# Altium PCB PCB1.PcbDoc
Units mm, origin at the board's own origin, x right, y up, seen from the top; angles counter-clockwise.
Board outline 49.91 x 77.34 mm, 4 copper layers (Top Layer, Layer 1, Layer 2, Bottom Layer), stack 0.787 mm thick; 22 components, 20 nets, 113 pads, 11 vias.
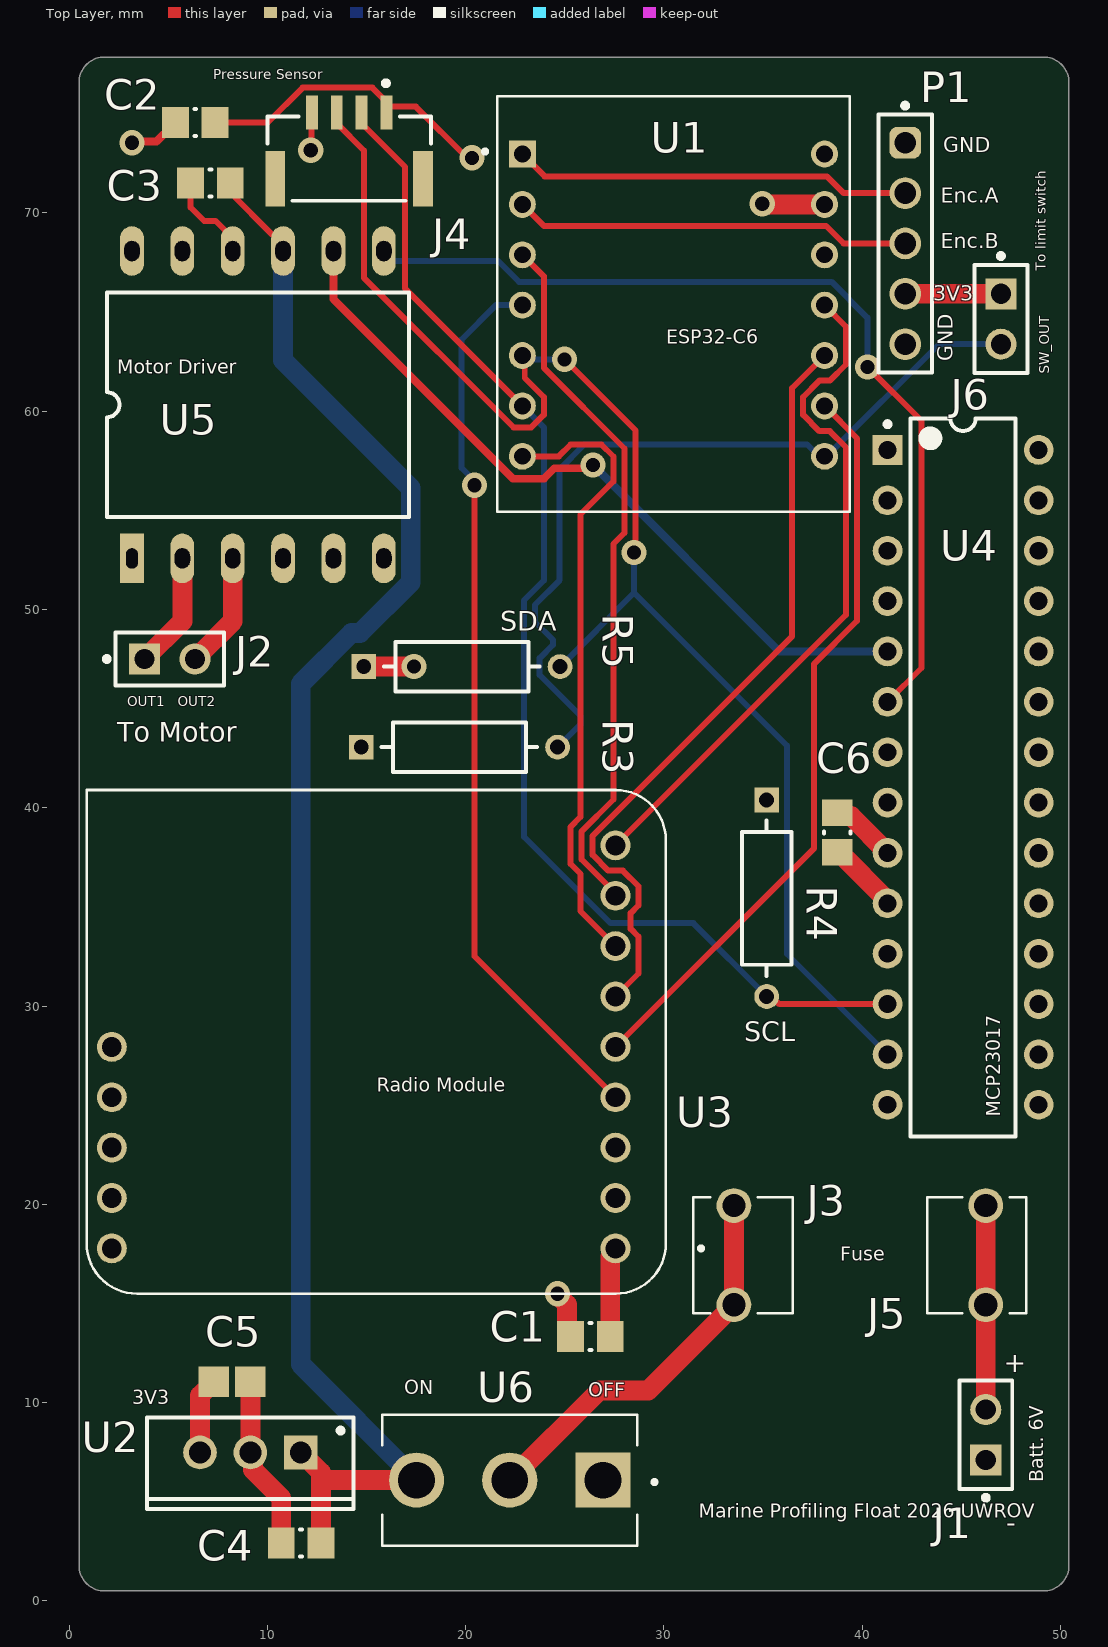
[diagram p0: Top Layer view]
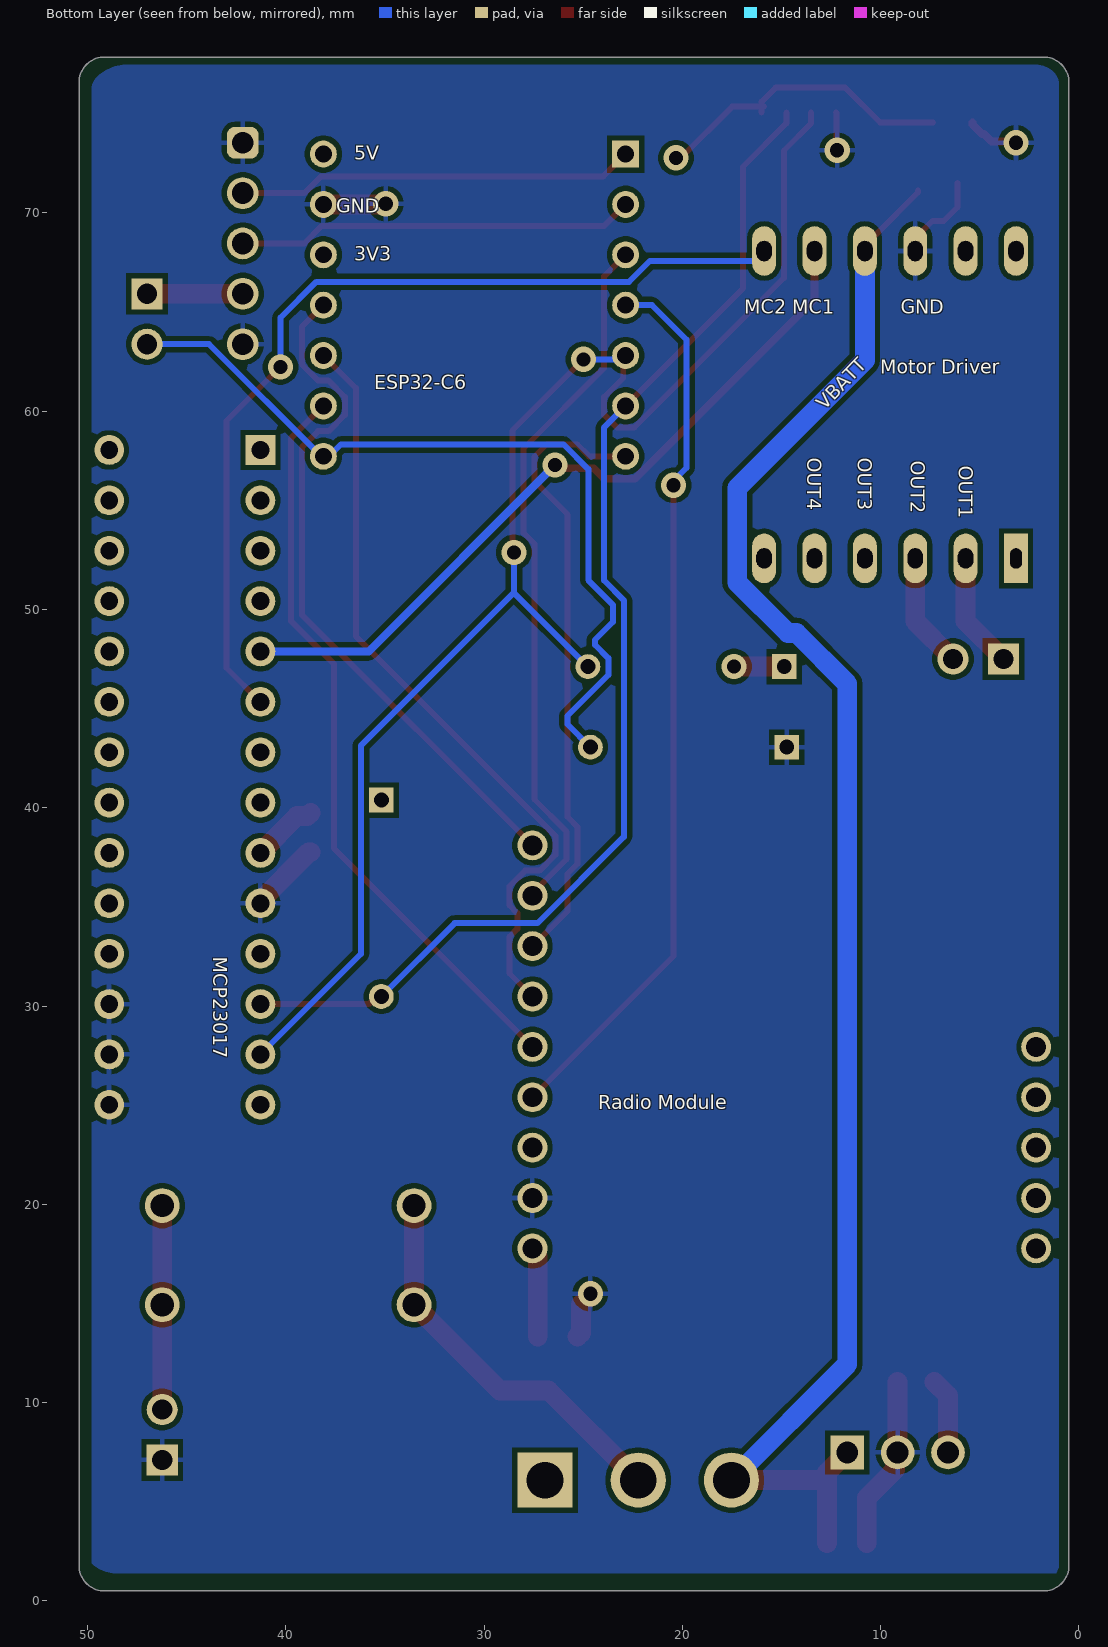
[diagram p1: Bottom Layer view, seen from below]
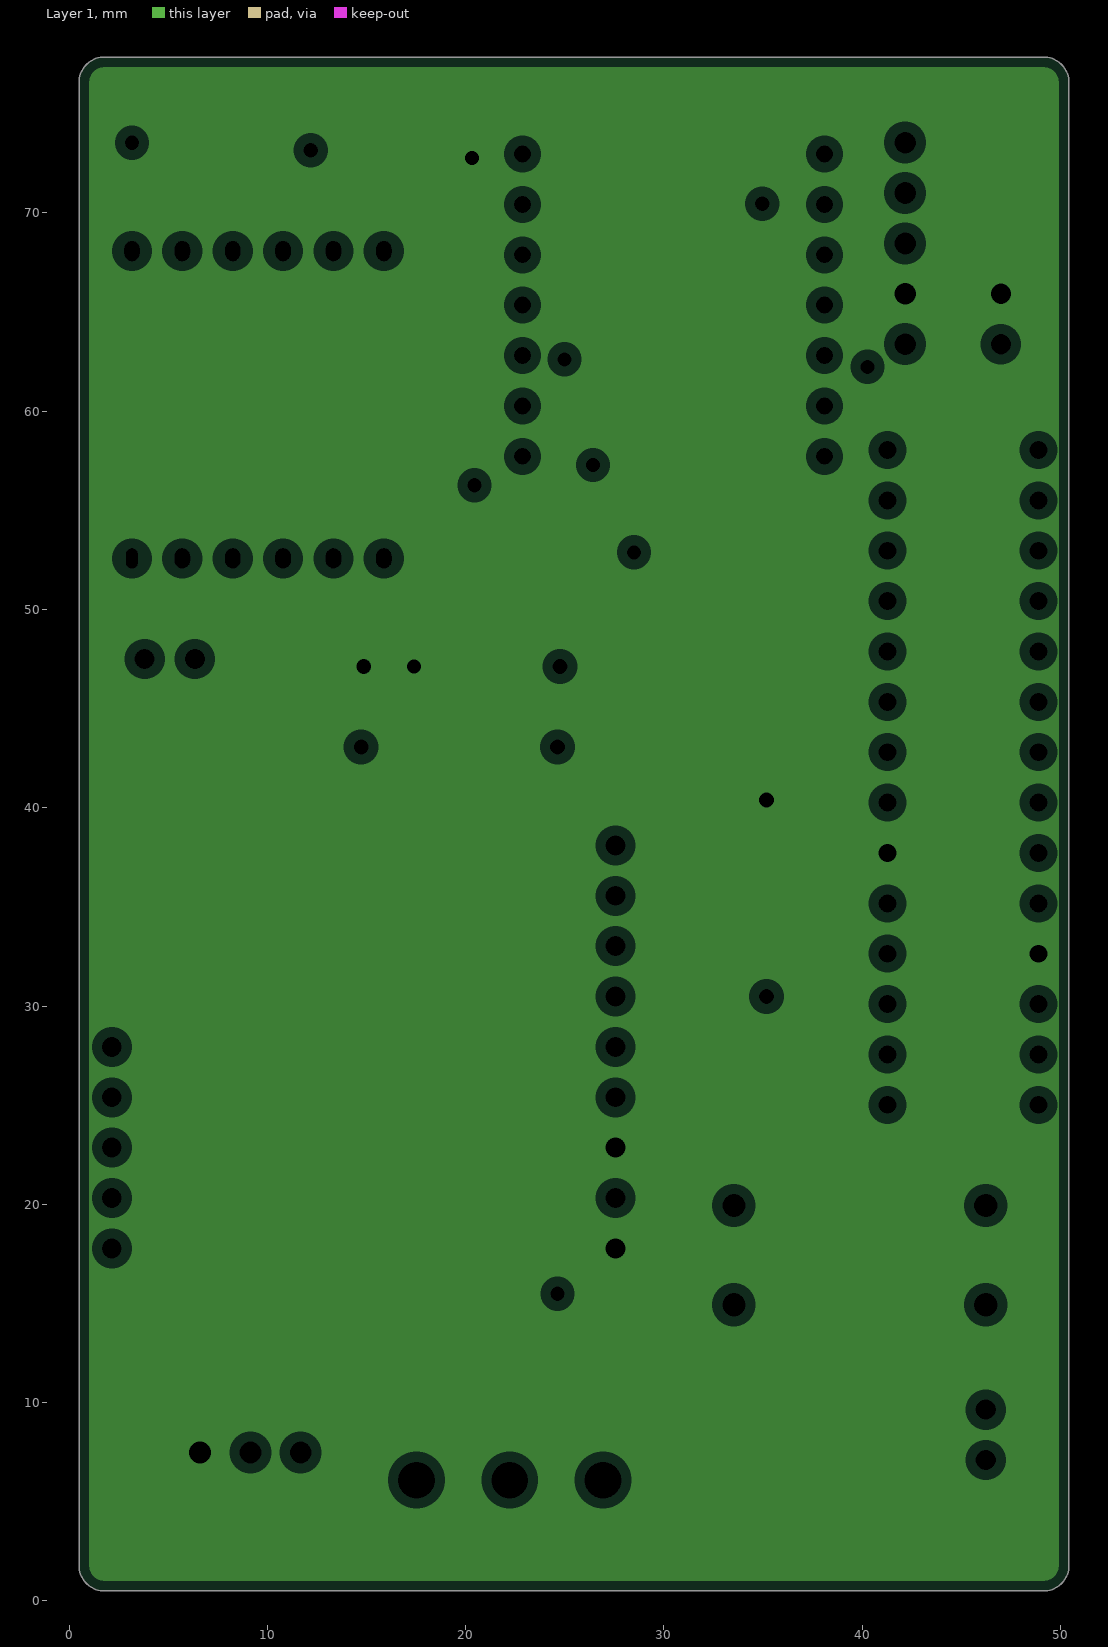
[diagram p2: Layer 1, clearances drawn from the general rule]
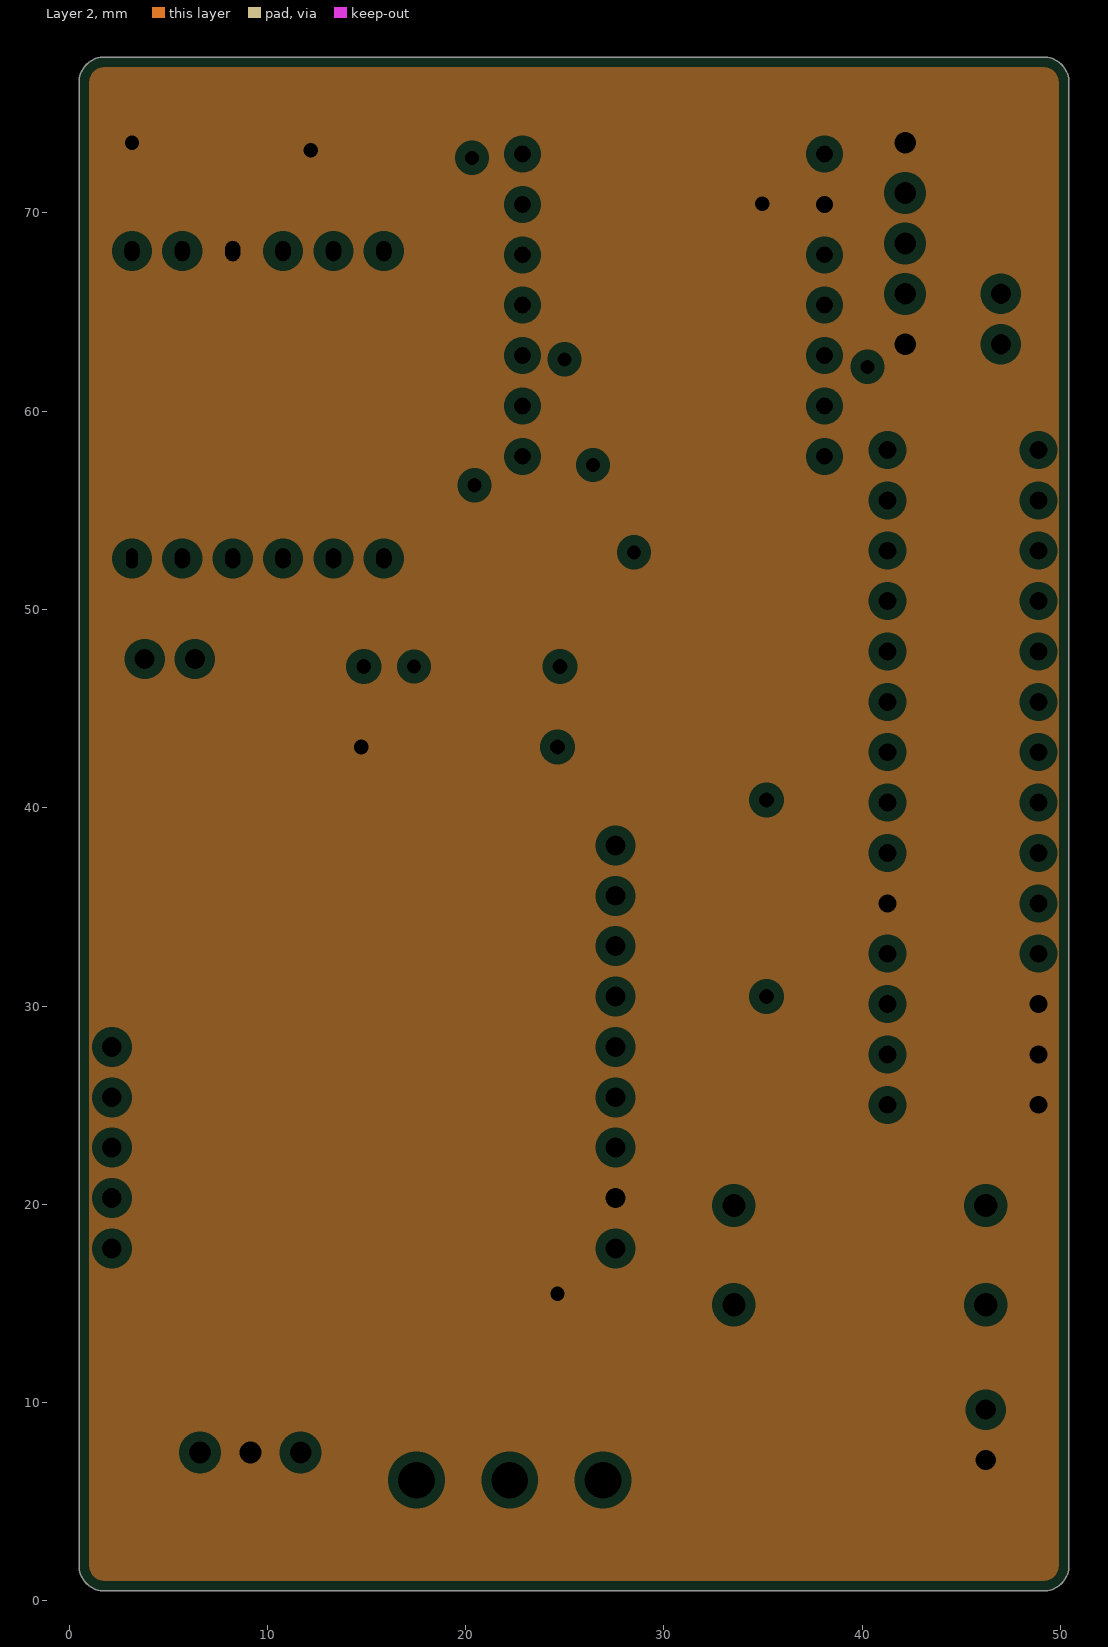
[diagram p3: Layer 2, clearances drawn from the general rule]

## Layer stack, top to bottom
Top Solder: solder mask 0.0102, Solder Resist, Dk 3.5
Top Layer: signal copper 0.0356
Dielectric 2: prepreg 0.1803, PP-021, Dk 4.4
Layer 1: plane copper 0.0175, net 3V3
Dielectric 1: dielectric 0.32, FR-4, Dk 4.8
Layer 2: plane copper 0.0175, net GND
Dielectric 3: prepreg 0.1803, PP-021, Dk 4.4
Bottom Layer: signal copper 0.0356
Bottom Solder: solder mask 0.0102, Solder Resist, Dk 3.5

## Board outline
0.508,1.778 0.508,76.581 cw(c1.778,76.581) 1.778,77.851 49.149,77.851 cw(c49.149,76.581) 50.419,76.581 50.419,1.778 cw(c49.149,1.778) 49.149,0.508 1.778,0.508 cw(c1.778,1.778)

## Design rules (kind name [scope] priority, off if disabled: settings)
Clearance [All] p1: gap=0.254 ignorepadtopadclearanceinfootprint=FALSE
PlaneClearance [All] p1: clearance=0.508
PlaneConnect [All] p1: planeconnectstyle=Relief reliefexpansion=0.508 reliefentries=4 reliefconductorwidth=0.254 reliefairgap=0.254
PolygonConnect [All] p1: connectstyle=Relief reliefconductorwidth=0.254 reliefentries=4 polygonreliefangle="90 Angle" airgapwidth=0.254
RoutingVias [All] p1: holewidth=0.711 width=1.27 viastyle="Through Hole" minholewidth=0.711 minwidth=1.27 maxholewidth=0.711 maxwidth=1.27
SolderMaskExpansion [All] p1: expansion=0.102 istentingtop=FALSE
SupplyNets "Schematic Supply Nets_1" [InNet('GND')] p1: voltage=0.000
SupplyNets "Schematic Supply Nets" [InNet('3V3')] p2: voltage=0.000
Width [All] p1: maxlimit=1 minlimit=0.254 preferedwidth=0.3
28 further rules are at their usual default settings.

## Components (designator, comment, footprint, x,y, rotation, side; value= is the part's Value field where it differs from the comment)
C1 "CAP 100nF 10V 0805(2012)" CAPC0805(2012)100_M 26.289,13.335 r0 top value=100nF
C2 "CAP 100nF 10V 0805(2012)" CAPC0805(2012)100_M 6.366,74.549 r0 top value=100nF
C3 "CAP 100nF 10V 0805(2012)" CAPC0805(2012)100_M 7.128,71.501 r180 top value=100nF
C4 "CAP 100nF 10V 0805(2012)" CAPC0805(2012)100_M 11.7,2.921 r0 top value=100nF
C5 "08053C225MAT2A" CAPC2013X152X50ML20T25 8.219,11.049 r180 top
C6 "CAP 100nF 10V 0805(2012)" CAPC0805(2012)100_M 38.735,38.751 r90 top value=100nF
J1 "TSW-102-07-F-S" FP-TSW-102-07-F-S-MFG 46.228,8.382 r90 top
J2 "TSW-102-07-F-S" FP-TSW-102-07-F-S-MFG 5.08,47.498 r0 top
J3 "Fuse Holder" FUSE_01110501Z 33.988,17.439 r0 top
J4 "BM04B-GHS-TBT(LF)(SN)" FP-BM04B-GHS-TBT_LF_SN-MFG 14.127,72.732 r0 top
J5 "Fuse Holder" FUSE_01110501Z 45.768,17.439 r180 top
J6 "TSW-102-07-F-S" FP-TSW-102-07-F-S-MFG 46.99,64.643 r270 top
P1 "61300511121" 61300511121 42.164,68.453 r270 top
R3 "RCMM024701GKS14" FP-RCMM02-MFG 19.685,43.053 r0 top
R4 "RCMM024701GKS14" FP-RCMM02-MFG 35.179,35.433 r270 top
R5 "RCMM024701GKS14" FP-RCMM02-MFG 19.812,47.117 r0 top
U1 "XIAO_ESP32_C6" MODULE_XIAO_ESP32C6 30.48,65.405 r0 top
U2 "LF33CV" TO220 9.144,7.493 r180 top
U3 "Component_1" RFM9X_LoRa 15.494,28.194 r180 top
U4 "MCP23017-E/SP" SPDIP300-SP28 45.085,41.529 r0 top
U5 "DRV8833" "DRV8833 Motor Driver" 3.175,52.572 r90 top
U6 "EG5137-ND" SW_500SSP1S2M2QEA 22.224,6.096 r180 top

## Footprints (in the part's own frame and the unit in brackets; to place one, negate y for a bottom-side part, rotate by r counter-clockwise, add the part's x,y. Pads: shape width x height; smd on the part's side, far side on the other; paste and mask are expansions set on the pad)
61300511121 [mm] "Pin Header, pitch 2.54 mm, THT, Vertical, single row, 5p"
  rrect50% 1.6x1.6 hole 1.1: 1(-5.08,0)
  round 1.6 hole 1.1: 2(-2.54,0) 3(0,0) 4(2.54,0) 5(5.08,0)
  silkscreen extent -7.07,-1.35 6.5,1.35, body extent -6.35,-1.27 6.35,1.27, height 8.57
CAPC0805(2012)100_M [mm] "Chip Capacitor, Body 2.0x1.2mm, Height 1.0mm, IPC Low Density"
  rect 1.35x1.55 smd: 1(-1,0) 2(1,0)
  silkscreen extent -0.05,-0.67 0.05,0.67, body extent -1.1,-0.72 1.1,0.72, height 1
CAPC2013X152X50ML20T25 [mm] "Chip Capacitor, 2-Leads, Body 2.01x1.25mm, IPC Low Density"
  rect 1.55x1.55 smd: 1(-0.925,0) 2(0.925,0)
  body extent -1.1,-0.72 1.11,0.72, height 1.52
"DRV8833 Motor Driver" [mm]
  rect 2.5x1.2 hole 0.6 slot 1.016 at 0 deg: 1(0,0)
  oval 2.5x1.2 hole 0.778 slot 1.016 at 0 deg: 2(0,-2.54) 3(0,-5.08) 4(0,-7.62) 5(0,-10.16) 6(0,-12.7) 7(15.5,-12.7) 8(15.5,-10.16) 9(15.5,-7.62) 10(15.5,-5.08) 11(15.5,-2.54) 12(15.5,0)
  silkscreen extent 2.08,-13.97 13.41,1.27
FP-BM04B-GHS-TBT_LF_SN-MFG [mm]
  rect 0.6x1.7 smd paste+0 mask+0: 1(1.875,2.325) 2(0.625,2.325) 3(-0.625,2.325) 4(-1.875,2.325)
  rect 1x2.8 smd paste+0 mask+0: 5(-3.725,-1.025) 6(3.725,-1.025)
  silkscreen extent -4.13,-2.12 4.13,3.92, body extent -4.33,-2.52 4.33,3.27, height 0.25
FP-RCMM02-MFG [mm]
  rect 1.25x1.25 hole 0.75 paste-2539.97 mask+0: 1(-4.95,0)
  round 1.25 hole 0.75 paste-2539.97 mask+0: 2(4.95,0)
  silkscreen extent -3.93,-1.25 3.93,1.25, body extent -5.68,-1.35 5.68,1.35, height 0.25
FP-TSW-102-07-F-S-MFG [mm]
  rect 1.57x1.57 hole 1.02 paste-2539.97 mask+0: 1(-1.27,0)
  round 1.57 hole 1.02 paste-2539.97 mask+0: 2(1.27,0)
  silkscreen extent -3.3,-1.34 2.73,1.34, body extent -2.83,-1.44 2.83,1.44, height 0.25
FUSE_01110501Z [mm]
  round 1.755 hole 1.17 mask+0.102: 1(-0.46,2.5) 2(-0.46,-2.5)
  silkscreen extent -2.5,-2.92 2.5,2.92
MODULE_XIAO_ESP32C6 [mm]
  rect 1.358x1.358 / inner round 1.358 / far side rect 1.358x1.358 hole 0.85 mask+0.102: 1(-7.62,7.556)
  round 1.358 hole 0.85 mask+0.102: 2(-7.62,5.016) 3(-7.62,2.476) 4(-7.62,-0.064) 5(-7.62,-2.603) 6(-7.62,-5.143) 7(-7.62,-7.683) 8(7.62,-7.683) 9(7.62,-5.143) 10(7.62,-2.603) 11(7.62,-0.064) 12(7.62,2.476) 13(7.62,5.016) 14(7.62,7.556)
  silkscreen extent -9.6,-10.48 8.89,10.48, body extent -8.89,-10.48 8.89,11.99, height 4.21
RFM9X_LoRa [mm] "RFM9X_LoRa"
  round 1.508 hole 1: U3_1(-12.065,10.414) U3_2(-12.065,7.874) U3_3(-12.065,5.334) U3_4(-12.065,2.794) U3_5(-12.065,0.254) U3_6(-12.065,-2.286) U3_7(-12.065,-4.826) U3_8(-12.065,-7.366) U3_9(-12.065,-9.906) U3_10(13.335,10.414) U3_11(13.335,7.874) U3_12(13.335,5.334) U3_13(13.335,2.794) U3_14(13.335,0.254)
  silkscreen extent -16.47,-12.7 14.61,12.7, body extent -14.61,-12.7 14.61,12.7, height 3.37
SPDIP300-SP28 [mm] "DIP, 28-Pin, Row Spacing 7.62 mm, Pitch 2.54 mm"
  rect 1.5x1.5 hole 0.9: 1(-3.81,16.51)
  round 1.5 hole 0.9: 2(-3.81,13.97) 3(-3.81,11.43) 4(-3.81,8.89) 5(-3.81,6.35) 6(-3.81,3.81) 7(-3.81,1.27) 8(-3.81,-1.27) 9(-3.81,-3.81) 10(-3.81,-6.35) 11(-3.81,-8.89) 12(-3.81,-11.43) 13(-3.81,-13.97) 14(-3.81,-16.51) 15(3.81,-16.51) 16(3.81,-13.97) 17(3.81,-11.43) 18(3.81,-8.89) 19(3.81,-6.35) 20(3.81,-3.81) 21(3.81,-1.27) 22(3.81,1.27) 23(3.81,3.81) 24(3.81,6.35) 25(3.81,8.89) 26(3.81,11.43) 27(3.81,13.97) 28(3.81,16.51)
  silkscreen extent -3.93,-18.1 2.65,18.1, body extent -3.55,-18.1 3.55,18.1, height 5.33
SW_500SSP1S2M2QEA [mm]
  rect 2.775x2.775 / inner round 2.775 / far side rect 2.775x2.775 hole 1.85 mask+0.102: 1(-4.7,0)
  round 2.775 hole 1.85 mask+0.102: 2(0,0) 3(4.7,0)
  silkscreen extent -7.4,-3.3 6.43,3.3
TO220 [mm] "TO, Thru-Hole, Vertical, Heatsink Mounted; 3 In-Line Leads; Pitch 2.54 mm"
  rect 1.7x1.7 hole 1.1: 1(-2.54,0)
  round 1.7 hole 1.1: 2(0,0) 3(2.54,0)
  silkscreen extent -5.2,-1.75 5.2,2.85, body extent -5.25,-1.8 5.25,2.9, height 19.7

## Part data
C1 C2 C3 C4 C6: library part CMP-1036-04393-1, "CAP 100nF 10V ±5% 0805 (2012 Metric) Thickness 1mm SMD", Case-EIA=0805, Case-Metric=2012, Rated Voltage="10 V", Tolerance=Â±5%
C5: library part CMP-2007-04515-1, Manufacturer="AVX Interconnect / Elco"
J1 J2 J6: library part CMP-02766-001458-1, "CONN HEADER VERT 2POS 2.54MM", Color=Black, Flammability Rating="UL94 V-0", Max Current Rating=7.6A, Max Operating Temperature=125°C, Max Voltage Rating (AC)=550V, Min Operating Temperature=-55°C, Package Quantity=1
J3 J5: library part Fuse_Holder
J4: library part CMP-17439-000062-2, "CONN HEADER SMD 4POS 1.25MM", Case/Package=SMD/SMT, Current Rating=1A, Housing Color=Natural, Max Operating Temperature=85°C, Min Operating Temperature=-25°C, Voltage Rating=50V
P1: library part CMP-1502-01068-4, "THT Vertical Pin Header WR-PHD, Pitch 2.54 mm, Single Row, 5 pins", Color=Black, Contact Resistance=20mΩ, Current Rating=3A, Max Operating Temperature=105°C, Min Operating Temperature=-40°C, Operating Supply Voltage=250V
R3 R4 R5: library part CMP-02408-000034-1, "RES 4.7K OHM 2% 1/2W AXIAL", Case/Package=Molded, Resistance=4.7kR, Resistor Type="Metal Film", Temperature Coefficient=100ppm/°C, Tolerance=2%
U1: "seeed studio FCC ID:Z4T-XIAOESP32C6"
U2: library part CMP-0244-00432-1, "500mA, Very Low Drop (0.45V) Voltage Regulator, 3.3V, 3-Pin TO-220"
U4: library part CMP-0186-00081-2, "16-Bit I/O Expander with Serial Interface, 28-Pin SPDIP, Extended Temperature"
U5: "Motor Driver 6.5V-45VDC In"
U6: library part 500SSP1S2M2QEA, "Switch Slide ON None ON SPDT Extended Top Slide 5A 250VAC 28VDC PC Pins Thru-Hole", Contact Current Rating=2A, Contact Resistance=10mΩ, Contact Voltage Rating (AC)=250V, Current Rating=5A, Insulation Resistance=1GΩ, Manufacturer=E-Switch, Max Operating Temperature=85°C, Max Voltage Rating (DC)=28V, Min Operating Temperature=-30°C, Voltage Rating (AC)=120V

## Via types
v1: diameter 1.27, hole 0.711, Top Layer to Bottom Layer, 11 vias

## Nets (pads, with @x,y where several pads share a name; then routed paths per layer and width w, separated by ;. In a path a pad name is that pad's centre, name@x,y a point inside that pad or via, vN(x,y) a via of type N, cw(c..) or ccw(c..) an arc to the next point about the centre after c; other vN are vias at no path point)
3V3: C1.2 C2.2 C5.2 C6.2 J4.1 J6.1 P1.4 R4.1 R5.1 U2.3 U3.U3_1 U3.U3_3 U4.9 U4.18 | length 34.9
  Top Layer w0.3: C2.2 10.023,74.549 11.785,76.311 15.298,76.311 16.002,75.607 J4.1 ; J4.1@15.875,75.35 17.487,75.35 20.066,72.771 v1(20.32,72.771)
  Top Layer w1: U2.3 6.604,10.359 C5.2 ; R5.1 v1(17.399,47.117) ; C1.2 27.289,17.373 27.559,17.643 U3.U3_1 ; C6.2 38.91,39.576 39.426,39.576 41.275,37.727 U4.9 ; P1.4 J6.1
ENCODER_A: P1.2 U1.1 | length 20.1
  Top Layer w0.3: U1.1 23.984,71.837 38.216,71.837 39.06,70.993 P1.2
ENCODER_B: P1.3 U1.2 | length 20.1
  Top Layer w0.3: U1.2 23.943,69.338 38.175,69.338 39.06,68.453 P1.3
GND: C1.1 C2.1 C3.2 C4.1 C5.1 C6.1 J1.1 J4.4 P1.1 P1.5 R3.1 U1.13 U2.2 U3.U3_2 U4.10 U4.15 U4.16 U4.17 U5.10 | length 27.3
  Top Layer w0.3: C3.2 6.128,70.276 6.819,69.585 7.392,69.585 8.255,68.722 U5.10 ; v1(12.192,73.152) 12.222,73.182 12.222,75.027 J4.4
  Top Layer w0.4: v1(3.175,73.533) 3.235,73.593 4.41,73.593 4.791,73.974 4.891,73.974 5.366,74.449 C2.1
  Top Layer w1: C5.1 U2.2 9.278,7.359 9.278,6.618 10.7,5.196 C4.1 ; v1(24.638,15.494) 24.638,15.421 25.114,14.945 25.114,13.51 C1.1 ; v1@34.925,70.485 34.989,70.421 U1.13 ; C6.1 38.835,37.751 41.275,35.311 U4.10
  other v1: 34.957,70.453
MC1: U4.5 U5.8 | length 38.3
  Top Layer w0.4: U5.8 13.335,65.644 22.391,56.588 23.941,56.588 24.47,57.118 26.257,57.118 v1(26.416,57.277)
  Bottom Layer w0.4: v1(26.416,57.277) 35.814,47.879 U4.5
MC2: U4.6 U5.7 | length 47
  Top Layer w0.3: v1(40.259,62.23) 42.983,59.506 42.983,47.047 U4.6
  Bottom Layer w0.3: U5.7 15.875,67.988 16.291,67.572 21.638,67.572 22.69,66.52 38.453,66.52 40.259,64.714 v1(40.259,62.23)
NetJ2_1: J2.1 U5.2 | length 5.9
  Top Layer w1: J2.1 5.715,49.403 U5.2
NetJ2_2: J2.2 U5.3 | length 5.9
  Top Layer w1: J2.2 8.255,49.403 U5.3
RADIO_CS: U1.3 U3.U3_8 | length 36.1
  Top Layer w0.3: U1.3 23.943,66.798 23.943,62.181 28.009,58.115 28.009,53.862 27.454,53.307 27.454,40.416 25.847,38.809 25.847,37.391 27.559,35.679 U3.U3_8
RADIO_G0_INT: U1.4 U3.U3_4 | length 45.2
  Top Layer w0.3: v1(20.447,56.261) 20.447,32.512 U3.U3_4
  Bottom Layer w0.3: v1(20.447,56.261) 20.447,56.479 19.789,57.137 19.789,63.604 21.526,65.341 U1.4
RADIO_MISO: U1.10 U3.U3_6 | length 39.4
  Top Layer w0.3: U3.U3_6 28.717,31.638 28.717,33.5 28.321,33.896 28.321,34.684 28.717,35.08 28.717,36.04 27.927,36.83 27.191,36.83 26.401,37.62 26.401,38.58 36.463,48.642 36.463,61.165 U1.10
RADIO_MOSI: U1.11 U3.U3_9 | length 34.9
  Top Layer w0.3: U3.U3_9 39.183,49.724 39.183,58.17 38.362,58.991 37.838,58.991 37.017,59.813 37.017,60.71 37.838,61.531 38.362,61.531 39.183,62.353 39.183,64.258 U1.11
RADIO_RST: U1.7 U3.U3_7 | length 31.6
  Top Layer w0.3: U1.7 24.699,57.721 25.294,58.316 26.846,58.316 27.455,57.707 27.455,56.454 25.791,54.791 25.791,39.537 25.293,39.039 25.293,37.161 25.791,36.663 25.791,34.788 U3.U3_7
RADIO_SCK: U1.9 U3.U3_5 | length 38
  Top Layer w0.3: U3.U3_5 37.556,37.937 37.556,47.241 39.737,49.422 39.737,58.625 U1.9
SCL: J4.2 R4.2 U1.6 U4.12 | length 62.6
  Top Layer w0.3: J4.2 14.752,74.507 16.948,72.311 16.948,66.174 U1.6 ; R4.2 35.436,30.483 35.82,30.099 U4.12
  Bottom Layer w0.3: U1.6 23.943,59.178 23.943,51.455 22.946,50.459 22.946,38.535 27.303,34.178 31.484,34.178 R4.2
SDA: J4.3 R5.2 U1.5 U4.13 | length 74.4
  Top Layer w0.3: J4.3 13.502,74.507 14.871,73.138 14.871,66.719 22.411,59.178 23.309,59.178 23.943,59.813 23.943,60.71 22.981,61.673 22.981,62.681 U1.5 ; v1(24.982,62.611) 28.575,59.018 28.575,52.959 v1(28.493,52.877)
  Bottom Layer w0.3: U1.5@22.479,62.611 v1(24.982,62.611) ; R5.2 28.493,50.848 ; v1(28.493,52.877) 28.493,50.848 ; U4.13 36.208,32.626 36.208,43.132 28.493,50.848
SWITCH_OUT: J6.2 R3.2 U1.8 | length 41.9
  Bottom Layer w0.3: R3.2 25.791,44.209 25.791,44.633 23.733,46.691 23.733,47.543 24.405,48.215 24.405,48.464 23.5,49.369 23.5,50.229 24.743,51.472 24.743,57.073 25.986,58.316 37.219,58.316 37.814,57.721 U1.8 38.215,57.721 43.867,63.373 J6.2
TERM_1: J3.1 J3.2 U6.2 | length 20
  Top Layer w1: U6.2 26.743,10.615 29.204,10.615 J3.2 J3.1
TERM_2: J1.2 J5.1 J5.2 | length 10.3
  Top Layer w1: J1.2 J5.1 J5.2
VBATT: C3.1 C4.2 U2.1 U5.9 U6.3 | length 83.3
  Top Layer w0.3: C3.1@8.128,71.12 8.128,71.02 10.254,68.894 10.379,68.894 10.795,68.478 U5.9
  Top Layer w1: U2.1 12.7,6.477 12.7,6.096 C4.2 ; 13.081,6.096 U6.3
  Bottom Layer w1: U5.9 10.795,62.562 17.229,56.128 17.229,51.361 14.676,48.808 14.237,48.808 11.684,46.255 11.684,11.936 U6.3
pads on no net: J4.5 J4.6 U1.12 U1.14 U3.U3_10 U3.U3_11 U3.U3_12 U3.U3_13 U3.U3_14 U4.1 U4.2 U4.3 U4.4 U4.7 U4.8 U4.11 U4.14 U4.19 U4.20 U4.21 U4.22 U4.23 U4.24 U4.25 U4.26 U4.27 U4.28 U5.1 U5.4 U5.5 U5.6 U5.11 U5.12 U6.1

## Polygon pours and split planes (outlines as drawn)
GND on Bottom Layer "GND_L04_P000" (solid, pour order 0): 48.558,1.397 ccw(c48.558,3.131) 49.784,1.905 49.784,76.222 ccw(c48.917,76.222) 49.53,76.835 ccw(c47.997,75.302) 47.997,77.47 2.19,77.47 ccw(c2.19,76.169) 1.27,77.089 ccw(c1.883,76.476) 1.016,76.476 1.016,1.704 ccw(c1.45,1.704) 1.143,1.397 1.016,1.704 ccw(c1.45,1.704) 1.143,1.397
GND on Layer 2 (split plane): 49.268,77.333 49.384,77.306 49.495,77.26 49.597,77.197 49.688,77.12 49.765,77.029 49.828,76.927 49.874,76.816 49.901,76.7 49.91,76.594 49.909,76.581 49.909,1.778 49.91,1.765 49.901,1.659 49.874,1.543 49.828,1.432 49.765,1.33 49.688,1.239 49.597,1.162 49.495,1.099 49.384,1.053 49.268,1.026 49.162,1.017 49.149,1.018 1.778,1.018 1.765,1.017 1.659,1.026 1.543,1.053 1.432,1.099 1.33,1.162 1.239,1.239 1.162,1.33 1.099,1.432 1.053,1.543 1.026,1.659 1.017,1.765 1.018,1.778 1.018,76.581 1.017,76.594 1.026,76.7 1.053,76.816 1.099,76.927 1.162,77.029 1.239,77.12 1.33,77.197 1.432,77.26 1.543,77.306 1.659,77.333 1.765,77.342 1.778,77.341 49.149,77.341 49.162,77.342
3V3 on Layer 1 (split plane): 49.268,77.333 49.384,77.306 49.495,77.26 49.597,77.197 49.688,77.12 49.765,77.029 49.828,76.927 49.874,76.816 49.901,76.7 49.91,76.594 49.909,76.581 49.909,1.778 49.91,1.765 49.901,1.659 49.874,1.543 49.828,1.432 49.765,1.33 49.688,1.239 49.597,1.162 49.495,1.099 49.384,1.053 49.268,1.026 49.162,1.017 49.149,1.018 1.778,1.018 1.765,1.017 1.659,1.026 1.543,1.053 1.432,1.099 1.33,1.162 1.239,1.239 1.162,1.33 1.099,1.432 1.053,1.543 1.026,1.659 1.017,1.765 1.018,1.778 1.018,76.581 1.017,76.594 1.026,76.7 1.053,76.816 1.099,76.927 1.162,77.029 1.239,77.12 1.33,77.197 1.432,77.26 1.543,77.306 1.659,77.333 1.765,77.342 1.778,77.341 49.149,77.341 49.162,77.342

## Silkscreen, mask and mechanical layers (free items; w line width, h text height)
Top Overlay:
  text "Pressure Sensor" at 7.262,76.731 h0.5
  text "GND" at 44.092,73.048 h0.75
  text "Enc.A" at 43.965,70.508 h0.75
  text "Enc.B" at 43.965,68.222 h0.75
  text "To limit switch" at 49.253,67.079 h0.5 r90
  text "3V3" at 43.584,65.555 h0.75
  text "ESP32-C6" at 30.122,63.396 h0.7
  text "GND" at 44.554,62.507 h0.75 r90
  text "Motor Driver" at 2.436,61.872 h0.7
  text "SW_OUT" at 49.424,61.872 h0.5 r90
  text "SDA" at 21.74,48.918 h1
  text "OUT1" at 2.944,45.108 h0.5
  text "OUT2" at 5.484,45.108 h0.5
  text "To Motor" at 2.436,43.33 h1
  text "SCL" at 34.059,28.217 h1
  text "Radio Module" at 15.517,25.677 h0.7
  text "MCP23017" at 46.967,24.407 h0.7 r90
  text "Fuse" at 38.885,17.168 h0.7
  text "+" at 47.14,11.54 h1
  text "ON" at 16.914,10.437 h0.7
  text "OFF" at 26.185,10.31 h0.7
  text "3V3" at 3.198,9.929 h0.7
  text "Batt. 6V" at 49.126,5.992 h0.7 r90
  text "Marine Profiling Float 2026 UWROV" at 31.75,4.191 h0.7
  text "-" at 47.267,3.46 h1
Bottom Overlay:
  text "5V" at 36.553,72.667 h0.7
  text "GND" at 37.442,70 h0.7
  text "3V3" at 36.553,67.587 h0.7
  text "GND" at 8.994,64.92 h0.7
  text "MC1" at 14.455,64.92 h0.7
  text "MC2" at 16.868,64.92 h0.7
  text "Motor Driver" at 10.01,61.872 h0.7
  text "ESP32-C6" at 35.537,61.11 h0.7
  text "VBATT" at 12.832,60.029 h0.7 r313.78
  text "OUT3" at 11.153,57.635 h0.7 r90
  text "OUT4" at 13.693,57.635 h0.7 r90
  text "OUT2" at 8.486,57.508 h0.7 r90
  text "OUT1" at 6.073,57.254 h0.7 r90
  text "MCP23017" at 43.665,32.489 h0.7 r90
  text "Radio Module" at 24.234,24.788 h0.7
Mechanical 1:
  lines w1: 0.508,1.778 ccw(c1.778,1.778) 1.778,0.508 49.149,0.508 ccw(c49.149,1.778) 50.419,1.778 50.419,76.581 ccw(c49.149,76.581) 49.149,77.851 4.064,77.851 1.778,77.851 ccw(c1.778,76.581) 0.508,76.581 0.508,1.778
